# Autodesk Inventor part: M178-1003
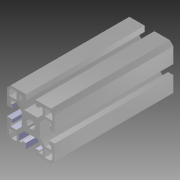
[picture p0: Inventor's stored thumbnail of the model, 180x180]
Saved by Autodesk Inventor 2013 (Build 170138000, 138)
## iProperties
Created: 2004-10
Material: Aluminium - 6061
Document SubType Name: Modeling
Designer: Autodesk, Inc.
Manufacturer: Standard
Standards Organization: Custom
Description: TABLE, SUPPORT BAR, SIDE
Stock Number: 10-040
Catalog Web Link: http://www.parker.com/ead/cm1.asp?cmid=809
Vendor: PARKER IPS
Part Number: M178-1003
Mass: 179.948 g
Surface Area: 483.565 cm^2
Volume: 66.4013 cm^3
Density: 2.71 g/cm^3
CAGE: 1LJX3
Dept. ID: Product Design
Description #2: ---
Finish #1: ---
Finish #2: ---
Material ID: ---
Project Number: ---
Length: 682.000 mm
Author: Autodesk, Inc.
Revision Number: A
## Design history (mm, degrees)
derived "40 Series Profiles.ipt"
feature "IPS40SeriesCutout1"
mirror "Mirror1"
body "Solid1"
tag "TaggingFeature2"
sketch "Sketch1"
  geometry: L1 (41, 291)-(20, 291) reference; L2 (20, -391)-(20, 291) reference; L3 (28, 291)-(28, -391) reference; L4 (20, 271)-(28, 271); C1 r 10 at (24, 271)
  constraints: 2 end point, 2 point on line, 1 centre point, 1 midpoint, 1 perpendicular
  dimensions: "d0" = 20 distance between parallel lines of L4 L1; "d1" = 20 diameter of C1
feature "Solid1::40 Series Profiles.ipt" dims "ScaleForDerivedMember" = 10
other parameters: "Length" = 682
